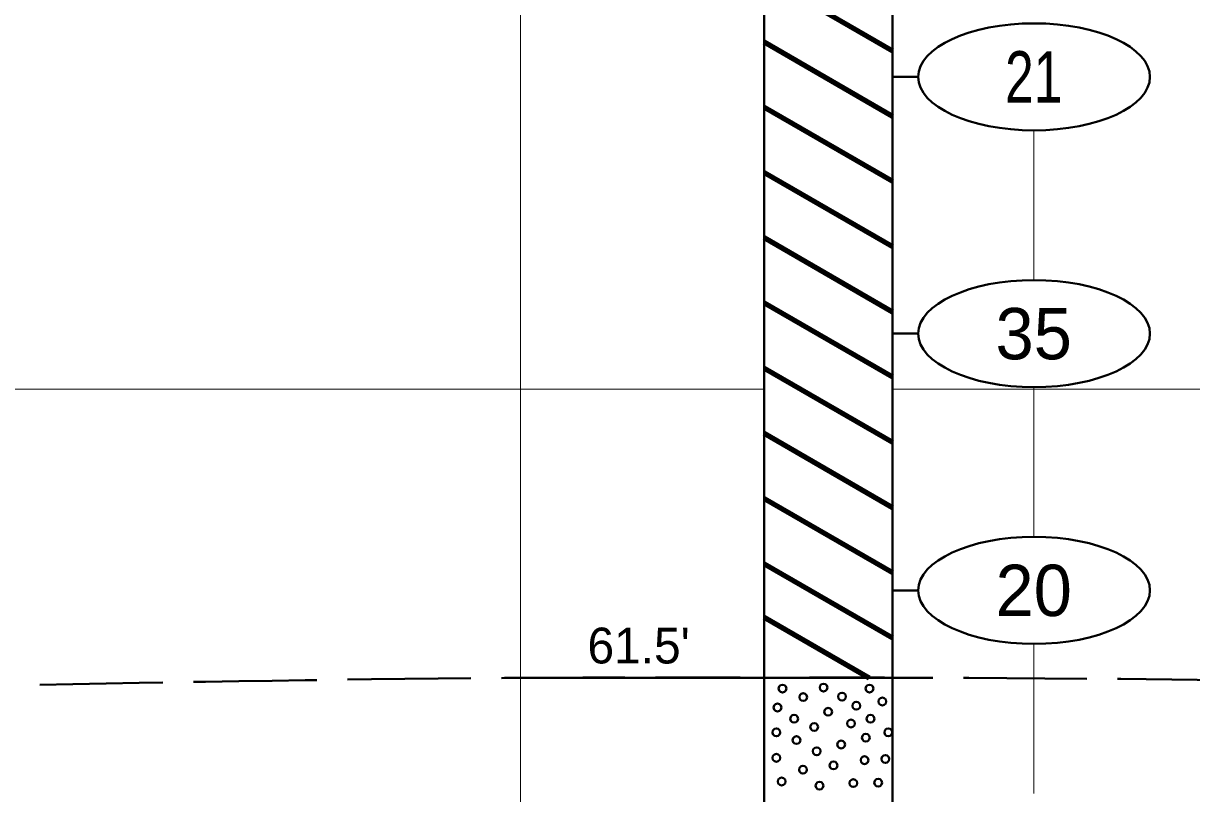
# Model space of a CAD drawing. Extents: x -582 to 653, y -817 to -3.
# Drawn here: x -185.45 to -162.69, y -253.35 to -238.35 of the extents above; entities that cross this region are included whole.
import ezdxf
from ezdxf.enums import TextEntityAlignment as Align

# ---------------------------------------------------------------- set-up
doc = ezdxf.new("R2010")
doc.units = 0
doc.header["$LTSCALE"] = 0.4
doc.linetypes.add('LONG_DASHED', pattern=[7.5, 6, -1.5])
for name, color, linetype, lineweight in [('26', 7, 'LONG_DASHED', 40), ('27', 7, 'Continuous', 40), ('7', 7, 'Continuous', 13)]:
    doc.layers.add(name, color=color, linetype=linetype, lineweight=lineweight)

msp = doc.modelspace()

# ---------------------------------------------------------------- linework, layer by layer
at = {"layer": '26'}
msp.add_spline([(-185.1304, -251.2306), (-174.783, -251.0929), (-171.0156, -251.0929), (-168.5156, -251.0929), (-144.783, -251.3429), (-141.0156, -251.3429), (-138.5156, -251.3429), (-125.834, -251.3429)], degree=3, dxfattribs=at)
at = {"layer": '27', "lineweight": 158}
for p, q in [((-171.0156, -237.4429), (-168.5156, -238.8863)), ((-171.0156, -238.7129), (-168.5156, -240.1563)), ((-171.0156, -239.9829), (-168.5156, -241.4263)), ((-171.0156, -241.2529), (-168.5156, -242.6963)), ((-171.0156, -242.5229), (-168.5156, -243.9663)), ((-171.0156, -243.7929), (-168.5156, -245.2363)), ((-171.0156, -245.0629), (-168.5156, -246.5063)), ((-171.0156, -246.3329), (-168.5156, -247.7763)), ((-171.0156, -247.6029), (-168.5156, -249.0463)), ((-171.0156, -248.8729), (-168.5156, -250.3163)), ((-171.0156, -249.9126), (-168.9714, -251.0929))]:
    msp.add_line(p, q, dxfattribs=at)
at = {"layer": '27'}
for p, q in [((-168.0156, -239.3929), (-168.5156, -239.3929)), ((-168.0156, -244.3929), (-168.5156, -244.3929)), ((-168.0156, -249.3929), (-168.5156, -249.3929)), ((-174.783, -251.0929), (-171.0156, -251.0929))]:
    msp.add_line(p, q, dxfattribs=at)
for points in [[(-171.0156, -231.0929), (-168.5156, -231.0929), (-168.5156, -251.0929), (-171.0156, -251.0929)], [(-171.0156, -251.0929), (-168.5156, -251.0929), (-168.5156, -259.3929), (-171.0156, -259.3929)], [(-170.5837, -251.3055), (-170.5939, -251.2674), (-170.6218, -251.2396), (-170.6599, -251.2293), (-170.698, -251.2396), (-170.7259, -251.2674), (-170.7361, -251.3055), (-170.7259, -251.3436), (-170.698, -251.3715), (-170.6599, -251.3817), (-170.6218, -251.3715), (-170.5939, -251.3436)], [(-169.7827, -251.286), (-169.7929, -251.2479), (-169.8208, -251.22), (-169.8589, -251.2098), (-169.897, -251.22), (-169.9249, -251.2479), (-169.9351, -251.286), (-169.9249, -251.3241), (-169.897, -251.3519), (-169.8589, -251.3622), (-169.8208, -251.3519), (-169.7929, -251.3241)], [(-168.8891, -251.3056), (-168.8993, -251.2675), (-168.9272, -251.2396), (-168.9653, -251.2294), (-169.0034, -251.2396), (-169.0313, -251.2675), (-169.0415, -251.3056), (-169.0313, -251.3437), (-169.0034, -251.3716), (-168.9653, -251.3818), (-168.9272, -251.3716), (-168.8993, -251.3437)], [(-170.1788, -251.4708), (-170.189, -251.4327), (-170.2169, -251.4048), (-170.255, -251.3946), (-170.2931, -251.4048), (-170.321, -251.4327), (-170.3312, -251.4708), (-170.321, -251.5089), (-170.2931, -251.5368), (-170.255, -251.547), (-170.2169, -251.5368), (-170.189, -251.5089)], [(-169.4237, -251.4618), (-169.4339, -251.4237), (-169.4618, -251.3958), (-169.4999, -251.3856), (-169.538, -251.3958), (-169.5659, -251.4237), (-169.5761, -251.4618), (-169.5659, -251.4999), (-169.538, -251.5278), (-169.4999, -251.538), (-169.4618, -251.5278), (-169.4339, -251.4999)], [(-168.6382, -251.5577), (-168.6484, -251.5196), (-168.6763, -251.4917), (-168.7144, -251.4815), (-168.7525, -251.4917), (-168.7804, -251.5196), (-168.7906, -251.5577), (-168.7804, -251.5958), (-168.7525, -251.6237), (-168.7144, -251.6339), (-168.6763, -251.6237), (-168.6484, -251.5958)], [(-170.6799, -251.6734), (-170.6901, -251.6353), (-170.718, -251.6074), (-170.7561, -251.5972), (-170.7942, -251.6074), (-170.8221, -251.6353), (-170.8323, -251.6734), (-170.8221, -251.7115), (-170.7942, -251.7394), (-170.7561, -251.7496), (-170.718, -251.7394), (-170.6901, -251.7115)], [(-169.6938, -251.7566), (-169.704, -251.7185), (-169.7319, -251.6906), (-169.77, -251.6804), (-169.8081, -251.6906), (-169.836, -251.7185), (-169.8462, -251.7566), (-169.836, -251.7947), (-169.8081, -251.8226), (-169.77, -251.8328), (-169.7319, -251.8226), (-169.704, -251.7947)], [(-169.1455, -251.6391), (-169.1557, -251.601), (-169.1836, -251.5731), (-169.2217, -251.5629), (-169.2598, -251.5731), (-169.2877, -251.601), (-169.2979, -251.6391), (-169.2877, -251.6772), (-169.2598, -251.7051), (-169.2217, -251.7153), (-169.1836, -251.7051), (-169.1557, -251.6772)], [(-170.357, -251.8921), (-170.3672, -251.854), (-170.3951, -251.8261), (-170.4332, -251.8159), (-170.4713, -251.8261), (-170.4992, -251.854), (-170.5094, -251.8921), (-170.4992, -251.9302), (-170.4713, -251.958), (-170.4332, -251.9683), (-170.3951, -251.958), (-170.3672, -251.9302)], [(-169.2497, -251.9849), (-169.2599, -251.9468), (-169.2878, -251.9189), (-169.3259, -251.9087), (-169.364, -251.9189), (-169.3919, -251.9468), (-169.4021, -251.9849), (-169.3919, -252.023), (-169.364, -252.0508), (-169.3259, -252.0611), (-169.2878, -252.0508), (-169.2599, -252.023)], [(-168.8683, -251.8921), (-168.8785, -251.854), (-168.9064, -251.8261), (-168.9445, -251.8159), (-168.9826, -251.8261), (-169.0105, -251.854), (-169.0207, -251.8921), (-169.0105, -251.9302), (-168.9826, -251.958), (-168.9445, -251.9683), (-168.9064, -251.958), (-168.8785, -251.9302)], [(-170.7028, -252.1577), (-170.713, -252.1196), (-170.7409, -252.0918), (-170.779, -252.0815), (-170.8171, -252.0918), (-170.845, -252.1196), (-170.8552, -252.1577), (-170.845, -252.1958), (-170.8171, -252.2237), (-170.779, -252.2339), (-170.7409, -252.2237), (-170.713, -252.1958)], [(-169.9654, -252.0535), (-169.9756, -252.0154), (-170.0035, -251.9875), (-170.0416, -251.9773), (-170.0797, -251.9875), (-170.1076, -252.0154), (-170.1178, -252.0535), (-170.1076, -252.0916), (-170.0797, -252.1195), (-170.0416, -252.1297), (-170.0035, -252.1195), (-169.9756, -252.0916)], [(-168.5225, -252.1577), (-168.5328, -252.1196), (-168.5606, -252.0918), (-168.5987, -252.0815), (-168.6368, -252.0918), (-168.6647, -252.1196), (-168.6749, -252.1577), (-168.6647, -252.1958), (-168.6368, -252.2237), (-168.5987, -252.2339), (-168.5606, -252.2237), (-168.5328, -252.1958)], [(-170.3112, -252.3078), (-170.3214, -252.2697), (-170.3493, -252.2418), (-170.3874, -252.2316), (-170.4255, -252.2418), (-170.4534, -252.2697), (-170.4636, -252.3078), (-170.4534, -252.3459), (-170.4255, -252.3737), (-170.3874, -252.384), (-170.3493, -252.3737), (-170.3214, -252.3459)], [(-169.4391, -252.3955), (-169.4493, -252.3574), (-169.4772, -252.3295), (-169.5153, -252.3193), (-169.5534, -252.3295), (-169.5813, -252.3574), (-169.5915, -252.3955), (-169.5813, -252.4336), (-169.5534, -252.4615), (-169.5153, -252.4717), (-169.4772, -252.4615), (-169.4493, -252.4336)], [(-168.9611, -252.262), (-168.9713, -252.2239), (-168.9992, -252.196), (-169.0373, -252.1858), (-169.0754, -252.196), (-169.1033, -252.2239), (-169.1135, -252.262), (-169.1033, -252.3001), (-169.0754, -252.328), (-169.0373, -252.3382), (-168.9992, -252.328), (-168.9713, -252.3001)], [(-170.7028, -252.6535), (-170.713, -252.6154), (-170.7409, -252.5876), (-170.779, -252.5773), (-170.8171, -252.5876), (-170.845, -252.6154), (-170.8552, -252.6535), (-170.845, -252.6916), (-170.8171, -252.7195), (-170.779, -252.7297), (-170.7409, -252.7195), (-170.713, -252.6916)], [(-169.9171, -252.5264), (-169.9273, -252.4883), (-169.9552, -252.4604), (-169.9933, -252.4502), (-170.0314, -252.4604), (-170.0593, -252.4883), (-170.0695, -252.5264), (-170.0593, -252.5645), (-170.0314, -252.5924), (-169.9933, -252.6026), (-169.9552, -252.5924), (-169.9273, -252.5645)], [(-168.5798, -252.6764), (-168.59, -252.6383), (-168.6179, -252.6104), (-168.656, -252.6002), (-168.6941, -252.6104), (-168.7219, -252.6383), (-168.7322, -252.6764), (-168.7219, -252.7145), (-168.6941, -252.7424), (-168.656, -252.7526), (-168.6179, -252.7424), (-168.59, -252.7145)], [(-170.1841, -252.8849), (-170.1943, -252.8468), (-170.2222, -252.8189), (-170.2603, -252.8087), (-170.2984, -252.8189), (-170.3263, -252.8468), (-170.3365, -252.8849), (-170.3263, -252.923), (-170.2984, -252.9509), (-170.2603, -252.9611), (-170.2222, -252.9509), (-170.1943, -252.923)], [(-169.5891, -252.801), (-169.5993, -252.7629), (-169.6272, -252.735), (-169.6653, -252.7248), (-169.7034, -252.735), (-169.7313, -252.7629), (-169.7415, -252.801), (-169.7313, -252.8391), (-169.7034, -252.867), (-169.6653, -252.8772), (-169.6272, -252.867), (-169.5993, -252.8391)], [(-168.984, -252.7006), (-168.9942, -252.6625), (-169.0221, -252.6346), (-169.0602, -252.6244), (-169.0983, -252.6346), (-169.1262, -252.6625), (-169.1364, -252.7006), (-169.1262, -252.7387), (-169.0983, -252.7666), (-169.0602, -252.7768), (-169.0221, -252.7666), (-168.9942, -252.7387)], [(-170.5998, -253.1163), (-170.61, -253.0782), (-170.6379, -253.0503), (-170.676, -253.0401), (-170.7141, -253.0503), (-170.742, -253.0782), (-170.7522, -253.1163), (-170.742, -253.1544), (-170.7141, -253.1823), (-170.676, -253.1925), (-170.6379, -253.1823), (-170.61, -253.1544)], [(-169.2039, -253.1455), (-169.2142, -253.1074), (-169.242, -253.0795), (-169.2801, -253.0693), (-169.3182, -253.0795), (-169.3461, -253.1074), (-169.3563, -253.1455), (-169.3461, -253.1836), (-169.3182, -253.2115), (-169.2801, -253.2217), (-169.242, -253.2115), (-169.2142, -253.1836)], [(-168.7183, -253.1379), (-168.7285, -253.0998), (-168.7564, -253.0719), (-168.7945, -253.0617), (-168.8326, -253.0719), (-168.8605, -253.0998), (-168.8707, -253.1379), (-168.8605, -253.176), (-168.8326, -253.2039), (-168.7945, -253.2141), (-168.7564, -253.2039), (-168.7285, -253.176)], [(-169.8612, -253.1964), (-169.8714, -253.1583), (-169.8993, -253.1304), (-169.9374, -253.1202), (-169.9755, -253.1304), (-170.0034, -253.1583), (-170.0136, -253.1964), (-170.0034, -253.2345), (-169.9755, -253.2624), (-169.9374, -253.2726), (-169.8993, -253.2624), (-169.8714, -253.2345)]]:
    msp.add_lwpolyline(points, close=True, dxfattribs=at)
for centre in [(-165.7583, -239.3929), (-165.7583, -244.3929), (-165.7583, -249.3929)]:
    msp.add_ellipse(centre, major_axis=(2.2574, 0), ratio=0.461538, dxfattribs=at)
at = {"layer": '7'}
for p, q in [((-175.7656, -315.4816), (-175.7656, -169.1034)), ((-165.7656, -243.351), (-165.7656, -240.4347)), ((-202.3744, -245.4729), (-171.0156, -245.4729)), ((-168.5156, -245.4729), (-141.0156, -245.4729)), ((-165.7656, -248.351), (-165.7656, -245.4347)), ((-165.7656, -253.351), (-165.7656, -250.4347))]:
    msp.add_line(p, q, dxfattribs=at)

# ---------------------------------------------------------------- texts
at = {"layer": '27', "width": 0.75}
msp.add_text('21', height=1, dxfattribs=at).set_placement((-165.7656, -239.8929), align=Align.CENTER)
at = {"layer": '27'}
for s, p in [('35', (-165.7657, -244.8929)), ('20', (-165.7656, -249.8929))]:
    msp.add_text(s, height=1, dxfattribs=at).set_placement(p, align=Align.CENTER)
msp.add_text("61.5'", height=0.6976, dxfattribs=at).set_placement((-174.4589, -250.8165))

doc.saveas('drawing.dxf')
